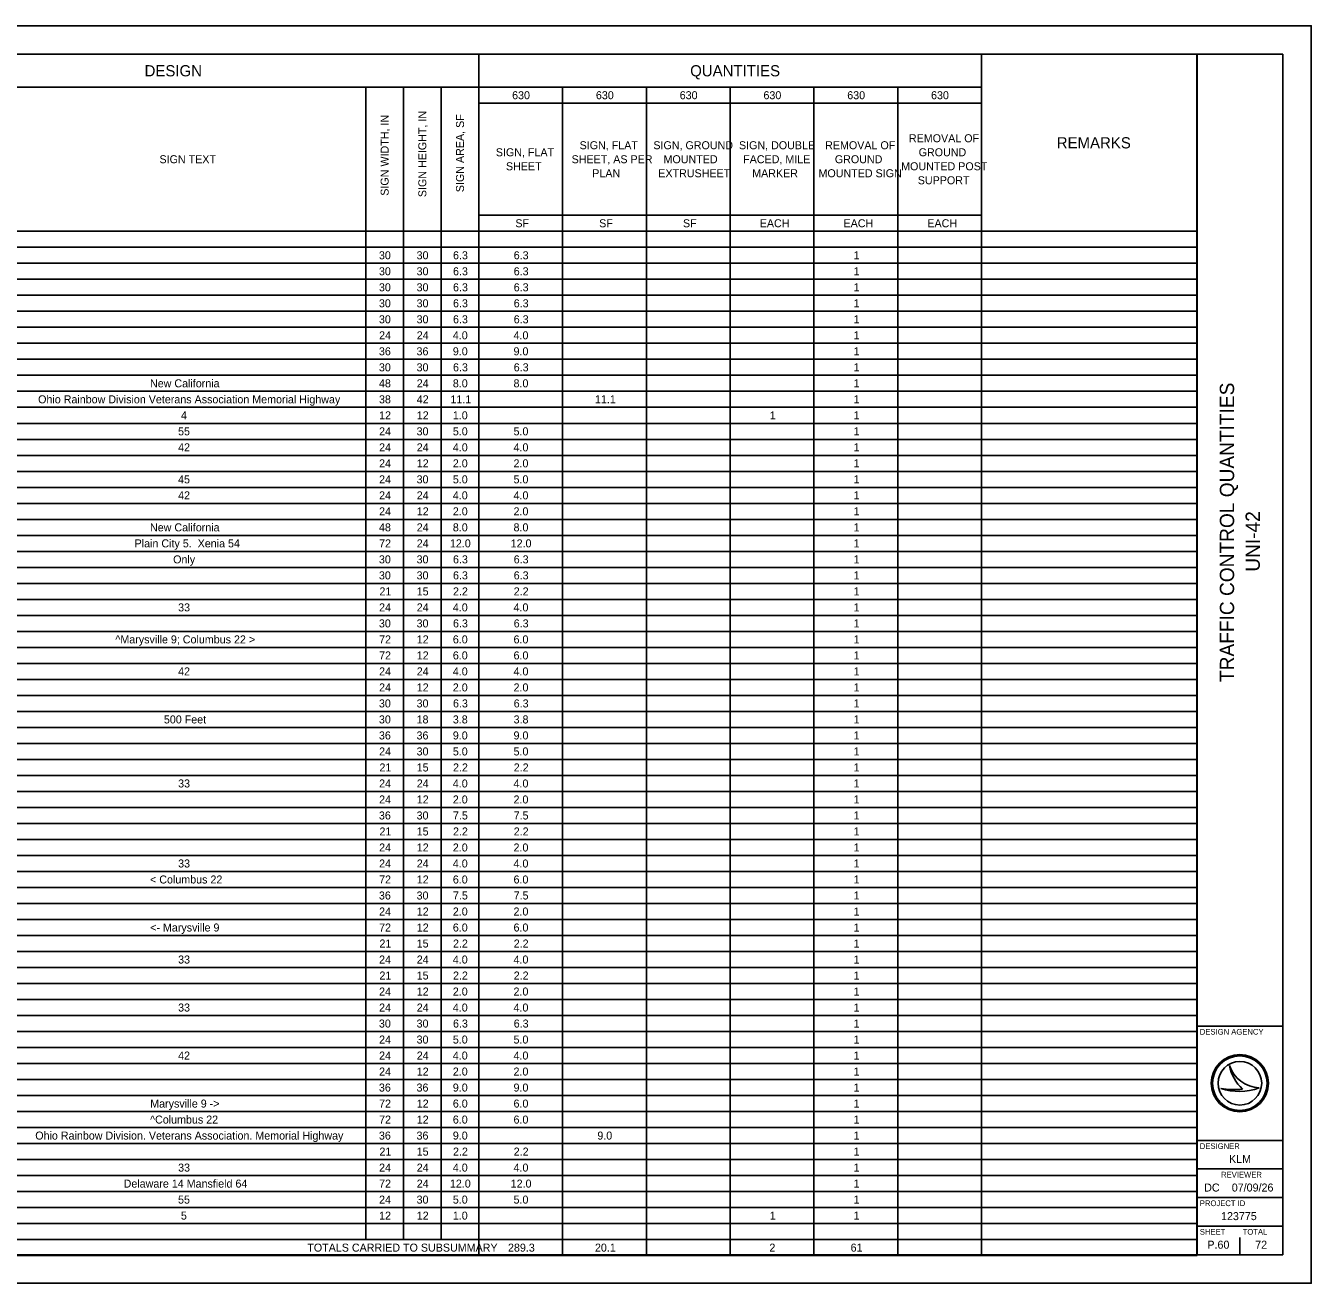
# Model space of a CAD drawing. Extents: x 0 to 34, y 0 to 22.
# Drawn here: x 11.51 to 34, y 0 to 22 of the extents above; entities that cross this region are included whole.
import ezdxf

# ---------------------------------------------------------------- set-up
doc = ezdxf.new("R2010")
doc.units = 0
for name, color, linetype in [('SH_Border', 7, 'Continuous'), ('SH_Cut_Line', 7, 'Continuous'), ('SH_Data', 7, 'Continuous'), ('SH_Text', 7, 'Continuous')]:
    doc.layers.add(name, color=color, linetype=linetype)

msp = doc.modelspace()

# ---------------------------------------------------------------- linework, layer by layer
at = {"layer": 'SH_Border'}
for p, q in [((32, 0.5), (32, 21.5)), ((32, 4.5), (33.5, 4.5)), ((32, 2.5), (33.5, 2.5)), ((32, 2), (33.5, 2)), ((32, 1.5), (33.5, 1.5)), ((32, 1), (33.5, 1))]:
    msp.add_line(p, q, dxfattribs=at)
msp.add_lwpolyline([(1.5, 21.5), (33.5, 21.5), (33.5, 0.5), (1.5, 0.5)], close=True, dxfattribs=at)
at = {"layer": 'SH_Cut_Line'}
msp.add_lwpolyline([(0, 0), (34, 0), (34, 22), (0, 22)], close=True, dxfattribs=at)
at = {"layer": 'SH_Data'}
for p, q in [((1.5, 21.5), (32.004, 21.5)), ((19.436, 21.5), (19.436, 0.484)), ((28.232, 21.5), (28.232, 0.484)), ((32.004, 21.5), (32.004, 0.484)), ((1.5, 20.924), (28.232, 20.924)), ((17.46, 20.924), (17.46, 0.764)), ((18.119, 20.924), (18.119, 0.764)), ((18.778, 20.924), (18.778, 0.764)), ((20.902, 20.924), (20.902, 0.484)), ((22.368, 20.924), (22.368, 0.484)), ((23.834, 20.924), (23.834, 0.484)), ((25.3, 20.924), (25.3, 0.484)), ((26.766, 20.924), (26.766, 0.484)), ((19.436, 20.644), (28.232, 20.644)), ((19.436, 18.684), (28.232, 18.684)), ((1.5, 18.404), (32.004, 18.404)), ((1.5, 18.124), (32.004, 18.124)), ((1.5, 17.844), (32.004, 17.844)), ((1.5, 17.564), (32.004, 17.564)), ((1.5, 17.284), (32.004, 17.284)), ((1.5, 17.004), (32.004, 17.004)), ((1.5, 16.724), (32.004, 16.724)), ((1.5, 16.444), (32.004, 16.444)), ((1.5, 16.164), (32.004, 16.164)), ((1.5, 15.884), (32.004, 15.884)), ((1.5, 15.604), (32.004, 15.604)), ((1.5, 15.324), (32.004, 15.324)), ((1.5, 15.044), (32.004, 15.044)), ((1.5, 14.764), (32.004, 14.764)), ((1.5, 14.484), (32.004, 14.484)), ((1.5, 14.204), (32.004, 14.204)), ((1.5, 13.924), (32.004, 13.924)), ((1.5, 13.644), (32.004, 13.644)), ((1.5, 13.364), (32.004, 13.364)), ((1.5, 13.084), (32.004, 13.084)), ((1.5, 12.804), (32.004, 12.804)), ((1.5, 12.524), (32.004, 12.524)), ((1.5, 12.244), (32.004, 12.244)), ((1.5, 11.964), (32.004, 11.964)), ((1.5, 11.684), (32.004, 11.684)), ((1.5, 11.404), (32.004, 11.404)), ((1.5, 11.124), (32.004, 11.124)), ((1.5, 10.844), (32.004, 10.844)), ((1.5, 10.564), (32.004, 10.564)), ((1.5, 10.284), (32.004, 10.284)), ((1.5, 10.004), (32.004, 10.004)), ((1.5, 9.724), (32.004, 9.724)), ((1.5, 9.444), (32.004, 9.444)), ((1.5, 9.164), (32.004, 9.164)), ((1.5, 8.884), (32.004, 8.884)), ((1.5, 8.604), (32.004, 8.604)), ((1.5, 8.324), (32.004, 8.324)), ((1.5, 8.044), (32.004, 8.044)), ((1.5, 7.764), (32.004, 7.764)), ((1.5, 7.484), (32.004, 7.484)), ((1.5, 7.204), (32.004, 7.204)), ((1.5, 6.924), (32.004, 6.924)), ((1.5, 6.644), (32.004, 6.644)), ((1.5, 6.364), (32.004, 6.364)), ((1.5, 6.084), (32.004, 6.084)), ((1.5, 5.804), (32.004, 5.804)), ((1.5, 5.524), (32.004, 5.524)), ((1.5, 5.244), (32.004, 5.244)), ((1.5, 4.964), (32.004, 4.964)), ((1.5, 4.684), (32.004, 4.684)), ((1.5, 4.404), (32.004, 4.404)), ((1.5, 4.124), (32.004, 4.124)), ((1.5, 3.844), (32.004, 3.844)), ((32.567, 3.81), (32.567, 3.81)), ((1.5, 3.564), (32.004, 3.564)), ((32.417, 3.41), (32.417, 3.41)), ((32.75, 3.5), (32.75, 3.5)), ((33.087, 3.419), (33.087, 3.419)), ((1.5, 3.284), (32.004, 3.284)), ((1.5, 3.004), (32.004, 3.004)), ((1.5, 2.724), (32.004, 2.724)), ((1.5, 2.444), (32.004, 2.444)), ((1.5, 2.164), (32.004, 2.164)), ((1.5, 1.884), (32.004, 1.884)), ((1.5, 1.604), (32.004, 1.604)), ((1.5, 1.324), (32.004, 1.324)), ((1.5, 1.044), (32.004, 1.044)), ((1.5, 0.764), (32.004, 0.764)), ((32.375, 0.675), (32.375, 0.675)), ((32.75, 0.5), (32.75, 0.8)), ((1.5, 0.484), (32.004, 0.484))]:
    msp.add_line(p, q, dxfattribs=at)
for radius in [0.5, 0.477, 0.477, 0.382]:
    msp.add_circle((32.75, 3.5), radius, dxfattribs=at)
for centre, radius, start, end in [((33.116, 3.998), 0.58, 198.9257, 198.9319), ((33.347, 3.97), 0.796, 191.6379, 191.6421), ((33.116, 3.998), 0.58, 198.9319, 267.1657), ((33.347, 3.97), 0.796, 191.6421, 226.0947), ((32.739, 4.37), 1.013, 251.4576, 290.0832), ((32.648, 4.654), 1.266, 259.4964, 259.4995), ((32.739, 4.37), 1.013, 251.4527, 251.4576), ((32.648, 4.654), 1.266, 259.4995, 276.6672)]:
    msp.add_arc(centre, radius, start, end, dxfattribs=at)

# ---------------------------------------------------------------- texts
for s, p in [('TRAFFIC CONTROL QUANTITIES', (32.65, 10.519)), ('UNI-42', (33.1, 12.448))]:
    msp.add_text(s, height=0.25, rotation=90, dxfattribs=at).set_placement(p)
for s, height, p in [('DESIGN AGENCY', 0.1, (32.05, 4.35)), ('DESIGNER', 0.1, (32.05, 2.35)), ('KLM', 0.14, (32.561, 2.105)), ('REVIEWER', 0.1, (32.422, 1.85)), ('DC', 0.14, (32.126, 1.605)), ('07/09/26', 0.14, (32.609, 1.605)), ('PROJECT ID', 0.1, (32.05, 1.35)), ('123775', 0.14, (32.421, 1.105)), ('SHEET', 0.1, (32.05, 0.85)), ('TOTAL', 0.1, (32.8, 0.85)), ('P.60', 0.14, (32.182, 0.605)), ('72', 0.14, (33.019, 0.605))]:
    msp.add_text(s, height=height, dxfattribs=at).set_placement(p)
at = {"layer": 'SH_Text'}
for s, height, p in [('DESIGN', 0.196, (13.589, 21.114)), ('QUANTITIES', 0.196, (23.134, 21.114)), ('630', 0.14, (20.019, 20.714)), ('630', 0.14, (21.485, 20.714)), ('630', 0.14, (22.951, 20.714)), ('630', 0.14, (24.416, 20.714)), ('630', 0.14, (25.882, 20.714)), ('630', 0.14, (27.348, 20.714)), ('REMOVAL OF ', 0.14, (26.961, 19.961)), ('REMARKS', 0.196, (29.547, 19.854)), ('SIGN, FLAT ', 0.14, (19.734, 19.716)), ('SIGN, FLAT ', 0.14, (21.2, 19.839)), ('SIGN, GROUND ', 0.14, (22.49, 19.839)), ('SIGN, DOUBLE ', 0.14, (23.988, 19.839)), ('REMOVAL OF ', 0.14, (25.495, 19.839)), ('GROUND ', 0.14, (27.131, 19.716)), ('SIGN TEXT', 0.14, (13.85, 19.594)), ('SHEET', 0.14, (19.911, 19.471)), ('SHEET, AS PER ', 0.14, (21.06, 19.594)), ('MOUNTED ', 0.14, (22.668, 19.594)), ('FACED, MILE ', 0.14, (24.061, 19.594)), ('GROUND ', 0.14, (25.665, 19.594)), ('MOUNTED POST ', 0.14, (26.825, 19.471)), ('PLAN', 0.14, (21.421, 19.349)), ('EXTRUSHEET', 0.14, (22.576, 19.349)), ('MARKER', 0.14, (24.219, 19.349)), ('MOUNTED SIGN', 0.14, (25.379, 19.349)), ('SUPPORT', 0.14, (27.116, 19.226)), ('SF', 0.14, (20.076, 18.474)), ('SF', 0.14, (21.542, 18.474)), ('SF', 0.14, (23.008, 18.474)), ('EACH', 0.14, (24.351, 18.474)), ('EACH', 0.14, (25.817, 18.474)), ('EACH', 0.14, (27.283, 18.474)), ('30', 0.14, (17.689, 17.914)), ('30', 0.14, (18.348, 17.914)), ('6.3', 0.14, (18.985, 17.914)), ('6.3', 0.14, (20.047, 17.914)), ('1', 0.14, (25.992, 17.914)), ('30', 0.14, (17.689, 17.634)), ('30', 0.14, (18.348, 17.634)), ('6.3', 0.14, (18.985, 17.634)), ('6.3', 0.14, (20.047, 17.634)), ('1', 0.14, (25.992, 17.634)), ('30', 0.14, (17.689, 17.354)), ('30', 0.14, (18.348, 17.354)), ('6.3', 0.14, (18.985, 17.354)), ('6.3', 0.14, (20.047, 17.354)), ('1', 0.14, (25.992, 17.354)), ('30', 0.14, (17.689, 17.074)), ('30', 0.14, (18.348, 17.074)), ('6.3', 0.14, (18.985, 17.074)), ('6.3', 0.14, (20.047, 17.074)), ('1', 0.14, (25.992, 17.074)), ('30', 0.14, (17.689, 16.794)), ('30', 0.14, (18.348, 16.794)), ('6.3', 0.14, (18.985, 16.794)), ('6.3', 0.14, (20.047, 16.794)), ('1', 0.14, (25.992, 16.794)), ('24', 0.14, (17.692, 16.514)), ('24', 0.14, (18.351, 16.514)), ('4.0', 0.14, (18.982, 16.514)), ('4.0', 0.14, (20.044, 16.514)), ('1', 0.14, (25.992, 16.514)), ('36', 0.14, (17.689, 16.234)), ('36', 0.14, (18.347, 16.234)), ('9.0', 0.14, (18.982, 16.234)), ('9.0', 0.14, (20.044, 16.234)), ('1', 0.14, (25.992, 16.234)), ('30', 0.14, (17.689, 15.954)), ('30', 0.14, (18.348, 15.954)), ('6.3', 0.14, (18.985, 15.954)), ('6.3', 0.14, (20.047, 15.954)), ('1', 0.14, (25.992, 15.954)), ('New California', 0.14, (13.684, 15.674)), ('48', 0.14, (17.69, 15.674)), ('24', 0.14, (18.351, 15.674)), ('8.0', 0.14, (18.982, 15.674)), ('8.0', 0.14, (20.044, 15.674)), ('1', 0.14, (25.992, 15.674)), ('Ohio Rainbow Division Veterans Association Memorial Highway', 0.14, (11.727, 15.394)), ('38', 0.14, (17.69, 15.394)), ('42', 0.14, (18.351, 15.394)), ('11.1', 0.14, (18.94, 15.394)), ('11.1', 0.14, (21.468, 15.394)), ('1', 0.14, (25.992, 15.394)), ('4', 0.14, (14.226, 15.114)), ('12', 0.14, (17.692, 15.114)), ('12', 0.14, (18.351, 15.114)), ('1.0', 0.14, (18.982, 15.114)), ('1', 0.14, (24.526, 15.114)), ('1', 0.14, (25.992, 15.114)), ('55', 0.14, (14.175, 14.834)), ('24', 0.14, (17.692, 14.834)), ('30', 0.14, (18.348, 14.834)), ('5.0', 0.14, (18.982, 14.834)), ('5.0', 0.14, (20.044, 14.834)), ('1', 0.14, (25.992, 14.834)), ('42', 0.14, (14.176, 14.554)), ('24', 0.14, (17.692, 14.554)), ('24', 0.14, (18.351, 14.554)), ('4.0', 0.14, (18.982, 14.554)), ('4.0', 0.14, (20.044, 14.554)), ('1', 0.14, (25.992, 14.554)), ('24', 0.14, (17.692, 14.274)), ('12', 0.14, (18.351, 14.274)), ('2.0', 0.14, (18.982, 14.274)), ('2.0', 0.14, (20.044, 14.274)), ('1', 0.14, (25.992, 14.274)), ('45', 0.14, (14.175, 13.994)), ('24', 0.14, (17.692, 13.994)), ('30', 0.14, (18.348, 13.994)), ('5.0', 0.14, (18.982, 13.994)), ('5.0', 0.14, (20.044, 13.994)), ('1', 0.14, (25.992, 13.994)), ('42', 0.14, (14.176, 13.714)), ('24', 0.14, (17.692, 13.714)), ('24', 0.14, (18.351, 13.714)), ('4.0', 0.14, (18.982, 13.714)), ('4.0', 0.14, (20.044, 13.714)), ('1', 0.14, (25.992, 13.714)), ('24', 0.14, (17.692, 13.434)), ('12', 0.14, (18.351, 13.434)), ('2.0', 0.14, (18.982, 13.434)), ('2.0', 0.14, (20.044, 13.434)), ('1', 0.14, (25.992, 13.434)), ('New California', 0.14, (13.684, 13.154)), ('48', 0.14, (17.69, 13.154)), ('24', 0.14, (18.351, 13.154)), ('8.0', 0.14, (18.982, 13.154)), ('8.0', 0.14, (20.044, 13.154)), ('1', 0.14, (25.992, 13.154)), ('Plain City 5.  Xenia 54', 0.14, (13.415, 12.874)), ('72', 0.14, (17.692, 12.874)), ('24', 0.14, (18.351, 12.874)), ('12.0', 0.14, (18.931, 12.874)), ('12.0', 0.14, (19.994, 12.874)), ('1', 0.14, (25.992, 12.874)), ('Only', 0.14, (14.089, 12.594)), ('30', 0.14, (17.689, 12.594)), ('30', 0.14, (18.348, 12.594)), ('6.3', 0.14, (18.985, 12.594)), ('6.3', 0.14, (20.047, 12.594)), ('1', 0.14, (25.992, 12.594)), ('30', 0.14, (17.689, 12.314)), ('30', 0.14, (18.348, 12.314)), ('6.3', 0.14, (18.985, 12.314)), ('6.3', 0.14, (20.047, 12.314)), ('1', 0.14, (25.992, 12.314)), ('21', 0.14, (17.698, 12.034)), ('15', 0.14, (18.35, 12.034)), ('2.2', 0.14, (18.985, 12.034)), ('2.2', 0.14, (20.047, 12.034)), ('1', 0.14, (25.992, 12.034)), ('33', 0.14, (14.176, 11.754)), ('24', 0.14, (17.692, 11.754)), ('24', 0.14, (18.351, 11.754)), ('4.0', 0.14, (18.982, 11.754)), ('4.0', 0.14, (20.044, 11.754)), ('1', 0.14, (25.992, 11.754)), ('30', 0.14, (17.689, 11.474)), ('30', 0.14, (18.348, 11.474)), ('6.3', 0.14, (18.985, 11.474)), ('6.3', 0.14, (20.047, 11.474)), ('1', 0.14, (25.992, 11.474)), ('^ Marysville 9; Columbus 22 >', 0.14, (13.078, 11.194)), ('72', 0.14, (17.692, 11.194)), ('12', 0.14, (18.351, 11.194)), ('6.0', 0.14, (18.982, 11.194)), ('6.0', 0.14, (20.044, 11.194)), ('1', 0.14, (25.992, 11.194)), ('72', 0.14, (17.692, 10.914)), ('12', 0.14, (18.351, 10.914)), ('6.0', 0.14, (18.982, 10.914)), ('6.0', 0.14, (20.044, 10.914)), ('1', 0.14, (25.992, 10.914)), ('42', 0.14, (14.176, 10.634)), ('24', 0.14, (17.692, 10.634)), ('24', 0.14, (18.351, 10.634)), ('4.0', 0.14, (18.982, 10.634)), ('4.0', 0.14, (20.044, 10.634)), ('1', 0.14, (25.992, 10.634)), ('24', 0.14, (17.692, 10.354)), ('12', 0.14, (18.351, 10.354)), ('2.0', 0.14, (18.982, 10.354)), ('2.0', 0.14, (20.044, 10.354)), ('1', 0.14, (25.992, 10.354)), ('30', 0.14, (17.689, 10.074)), ('30', 0.14, (18.348, 10.074)), ('6.3', 0.14, (18.985, 10.074)), ('6.3', 0.14, (20.047, 10.074)), ('1', 0.14, (25.992, 10.074)), ('500 Feet', 0.14, (13.927, 9.794)), ('30', 0.14, (17.689, 9.794)), ('18', 0.14, (18.348, 9.794)), ('3.8', 0.14, (18.982, 9.794)), ('3.8', 0.14, (20.045, 9.794)), ('1', 0.14, (25.992, 9.794)), ('36', 0.14, (17.689, 9.514)), ('36', 0.14, (18.347, 9.514)), ('9.0', 0.14, (18.982, 9.514)), ('9.0', 0.14, (20.044, 9.514)), ('1', 0.14, (25.992, 9.514)), ('24', 0.14, (17.692, 9.234)), ('30', 0.14, (18.348, 9.234)), ('5.0', 0.14, (18.982, 9.234)), ('5.0', 0.14, (20.044, 9.234)), ('1', 0.14, (25.992, 9.234)), ('21', 0.14, (17.698, 8.954)), ('15', 0.14, (18.35, 8.954)), ('2.2', 0.14, (18.985, 8.954)), ('2.2', 0.14, (20.047, 8.954)), ('1', 0.14, (25.992, 8.954)), ('33', 0.14, (14.176, 8.674)), ('24', 0.14, (17.692, 8.674)), ('24', 0.14, (18.351, 8.674)), ('4.0', 0.14, (18.982, 8.674)), ('4.0', 0.14, (20.044, 8.674)), ('1', 0.14, (25.992, 8.674)), ('24', 0.14, (17.692, 8.394)), ('12', 0.14, (18.351, 8.394)), ('2.0', 0.14, (18.982, 8.394)), ('2.0', 0.14, (20.044, 8.394)), ('1', 0.14, (25.992, 8.394)), ('36', 0.14, (17.689, 8.114)), ('30', 0.14, (18.348, 8.114)), ('7.5', 0.14, (18.984, 8.114)), ('7.5', 0.14, (20.046, 8.114)), ('1', 0.14, (25.992, 8.114)), ('21', 0.14, (17.698, 7.834)), ('15', 0.14, (18.35, 7.834)), ('2.2', 0.14, (18.985, 7.834)), ('2.2', 0.14, (20.047, 7.834)), ('1', 0.14, (25.992, 7.834)), ('24', 0.14, (17.692, 7.554)), ('12', 0.14, (18.351, 7.554)), ('2.0', 0.14, (18.982, 7.554)), ('2.0', 0.14, (20.044, 7.554)), ('1', 0.14, (25.992, 7.554)), ('33', 0.14, (14.176, 7.274)), ('24', 0.14, (17.692, 7.274)), ('24', 0.14, (18.351, 7.274)), ('4.0', 0.14, (18.982, 7.274)), ('4.0', 0.14, (20.044, 7.274)), ('1', 0.14, (25.992, 7.274)), ('< Columbus 22', 0.14, (13.685, 6.994)), ('72', 0.14, (17.692, 6.994)), ('12', 0.14, (18.351, 6.994)), ('6.0', 0.14, (18.982, 6.994)), ('6.0', 0.14, (20.044, 6.994)), ('1', 0.14, (25.992, 6.994)), ('36', 0.14, (17.689, 6.714)), ('30', 0.14, (18.348, 6.714)), ('7.5', 0.14, (18.984, 6.714)), ('7.5', 0.14, (20.046, 6.714)), ('1', 0.14, (25.992, 6.714)), ('24', 0.14, (17.692, 6.434)), ('12', 0.14, (18.351, 6.434)), ('2.0', 0.14, (18.982, 6.434)), ('2.0', 0.14, (20.044, 6.434)), ('1', 0.14, (25.992, 6.434)), ('<- Marysville 9', 0.14, (13.687, 6.154)), ('72', 0.14, (17.692, 6.154)), ('12', 0.14, (18.351, 6.154)), ('6.0', 0.14, (18.982, 6.154)), ('6.0', 0.14, (20.044, 6.154)), ('1', 0.14, (25.992, 6.154)), ('21', 0.14, (17.698, 5.874)), ('15', 0.14, (18.35, 5.874)), ('2.2', 0.14, (18.985, 5.874)), ('2.2', 0.14, (20.047, 5.874)), ('1', 0.14, (25.992, 5.874)), ('33', 0.14, (14.176, 5.594)), ('24', 0.14, (17.692, 5.594)), ('24', 0.14, (18.351, 5.594)), ('4.0', 0.14, (18.982, 5.594)), ('4.0', 0.14, (20.044, 5.594)), ('1', 0.14, (25.992, 5.594)), ('21', 0.14, (17.698, 5.314)), ('15', 0.14, (18.35, 5.314)), ('2.2', 0.14, (18.985, 5.314)), ('2.2', 0.14, (20.047, 5.314)), ('1', 0.14, (25.992, 5.314)), ('24', 0.14, (17.692, 5.034)), ('12', 0.14, (18.351, 5.034)), ('2.0', 0.14, (18.982, 5.034)), ('2.0', 0.14, (20.044, 5.034)), ('1', 0.14, (25.992, 5.034)), ('33', 0.14, (14.176, 4.754)), ('24', 0.14, (17.692, 4.754)), ('24', 0.14, (18.351, 4.754)), ('4.0', 0.14, (18.982, 4.754)), ('4.0', 0.14, (20.044, 4.754)), ('1', 0.14, (25.992, 4.754)), ('30', 0.14, (17.689, 4.474)), ('30', 0.14, (18.348, 4.474)), ('6.3', 0.14, (18.985, 4.474)), ('6.3', 0.14, (20.047, 4.474)), ('1', 0.14, (25.992, 4.474)), ('24', 0.14, (17.692, 4.194)), ('30', 0.14, (18.348, 4.194)), ('5.0', 0.14, (18.982, 4.194)), ('5.0', 0.14, (20.044, 4.194)), ('1', 0.14, (25.992, 4.194)), ('42', 0.14, (14.176, 3.914)), ('24', 0.14, (17.692, 3.914)), ('24', 0.14, (18.351, 3.914)), ('4.0', 0.14, (18.982, 3.914)), ('4.0', 0.14, (20.044, 3.914)), ('1', 0.14, (25.992, 3.914)), ('24', 0.14, (17.692, 3.634)), ('12', 0.14, (18.351, 3.634)), ('2.0', 0.14, (18.982, 3.634)), ('2.0', 0.14, (20.044, 3.634)), ('1', 0.14, (25.992, 3.634)), ('36', 0.14, (17.689, 3.354)), ('36', 0.14, (18.347, 3.354)), ('9.0', 0.14, (18.982, 3.354)), ('9.0', 0.14, (20.044, 3.354)), ('1', 0.14, (25.992, 3.354)), ('Marysville 9 ->', 0.14, (13.688, 3.074)), ('72', 0.14, (17.692, 3.074)), ('12', 0.14, (18.351, 3.074)), ('6.0', 0.14, (18.982, 3.074)), ('6.0', 0.14, (20.044, 3.074)), ('1', 0.14, (25.992, 3.074)), ('^ Columbus 22', 0.14, (13.685, 2.794)), ('72', 0.14, (17.692, 2.794)), ('12', 0.14, (18.351, 2.794)), ('6.0', 0.14, (18.982, 2.794)), ('6.0', 0.14, (20.044, 2.794)), ('1', 0.14, (25.992, 2.794)), ('Ohio Rainbow Division. Veterans Association. Memorial Highway', 0.14, (11.677, 2.514)), ('36', 0.14, (17.689, 2.514)), ('36', 0.14, (18.347, 2.514)), ('9.0', 0.14, (18.982, 2.514)), ('9.0', 0.14, (21.51, 2.514)), ('1', 0.14, (25.992, 2.514)), ('21', 0.14, (17.698, 2.234)), ('15', 0.14, (18.35, 2.234)), ('2.2', 0.14, (18.985, 2.234)), ('2.2', 0.14, (20.047, 2.234)), ('1', 0.14, (25.992, 2.234)), ('33', 0.14, (14.176, 1.954)), ('24', 0.14, (17.692, 1.954)), ('24', 0.14, (18.351, 1.954)), ('4.0', 0.14, (18.982, 1.954)), ('4.0', 0.14, (20.044, 1.954)), ('1', 0.14, (25.992, 1.954)), ('Delaware 14 Mansfield 64', 0.14, (13.223, 1.674)), ('72', 0.14, (17.692, 1.674)), ('24', 0.14, (18.351, 1.674)), ('12.0', 0.14, (18.931, 1.674)), ('12.0', 0.14, (19.994, 1.674)), ('1', 0.14, (25.992, 1.674)), ('55', 0.14, (14.175, 1.394)), ('24', 0.14, (17.692, 1.394)), ('30', 0.14, (18.348, 1.394)), ('5.0', 0.14, (18.982, 1.394)), ('5.0', 0.14, (20.044, 1.394)), ('1', 0.14, (25.992, 1.394)), ('5', 0.14, (14.225, 1.114)), ('12', 0.14, (17.692, 1.114)), ('12', 0.14, (18.351, 1.114)), ('1.0', 0.14, (18.982, 1.114)), ('1', 0.14, (24.526, 1.114)), ('1', 0.14, (25.992, 1.114)), ('TOTALS CARRIED TO SUBSUMMARY', 0.14, (16.436, 0.554)), ('289.3', 0.14, (19.947, 0.554)), ('20.1', 0.14, (21.468, 0.554)), ('2', 0.14, (24.52, 0.554)), ('61', 0.14, (25.941, 0.554))]:
    msp.add_text(s, height=height, dxfattribs=at).set_placement(p)
for s, p in [('SIGN HEIGHT, IN', (18.518, 19.001)), ('SIGN WIDTH, IN', (17.859, 19.026)), ('SIGN AREA, SF', (19.177, 19.088))]:
    msp.add_text(s, height=0.14, rotation=90, dxfattribs=at).set_placement(p)

doc.saveas('drawing.dxf')
